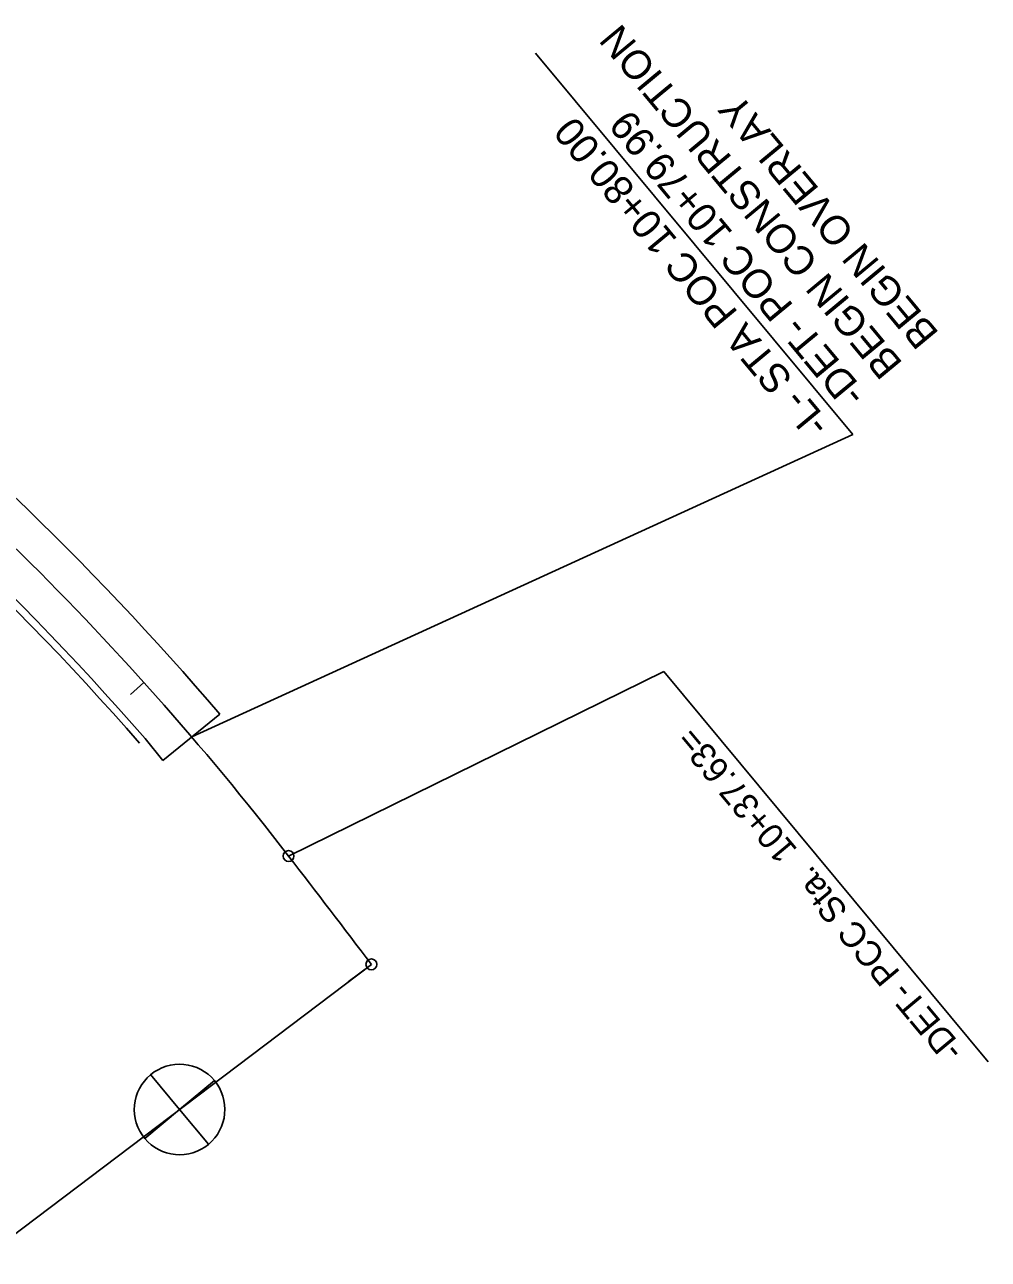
# Model space of a CAD drawing. Extents: x 2597390 to 2598563, y 852595 to 853909.
# Drawn here: x 2598297.5 to 2598563.3, y 852756.5 to 853097.3 of the extents above; entities that cross this region are included whole.
import ezdxf

# ---------------------------------------------------------------- set-up
doc = ezdxf.new("R2010")
doc.units = 0
for name, color, linetype in [('Prop DSN Text', 7, 'Continuous'), ('Prop EOT', 7, 'Continuous'), ('Prop Equation Symbol CELL', 7, 'Continuous'), ('Prop Horizontal Alignment', 7, 'Continuous'), ('Prop Horizontal Alignment Station Label', 7, 'Continuous'), ('Prop Horizontal Alignment Tick Large', 7, 'Continuous'), ('Prop Horizontal Alignment Tick Small', 7, 'Continuous'), ('Prop Lane Lines', 7, 'Continuous'), ('Prop Leader Line Medium', 7, 'Continuous'), ('Prop Paved Shoulder', 7, 'Continuous')]:
    doc.layers.add(name, color=color, linetype=linetype)

msp = doc.modelspace()

# ---------------------------------------------------------------- linework, layer by layer
at = {"layer": 'Prop EOT'}
for p, q in [((2598351.3, 852907), (2598335.58, 852894.18)), ((2598335.58, 852894.18), (2598330.68, 852900.27))]:
    msp.add_line(p, q, dxfattribs=at)
msp.add_arc((2597710.69, 852359.03), 823, 41.12046, 53.47068, dxfattribs=at)
at = {"layer": 'Prop Equation Symbol CELL'}
for p, q in [((2598332.2, 852807.45), (2598340.18, 852797.83)), ((2598349.8, 852805.82), (2598340.18, 852797.83)), ((2598340.18, 852797.83), (2598330.57, 852789.85)), ((2598340.18, 852797.83), (2598348.17, 852788.22))]:
    msp.add_line(p, q, dxfattribs=at)
for start, end in [(39.7011, 129.7056), (129.7011, 219.7056), (309.7011, 39.7056), (219.7011, 309.7056)]:
    msp.add_arc((2598340.18, 852797.83), 12.5, start, end, dxfattribs=at)
at = {"layer": 'Prop Horizontal Alignment'}
for centre, radius, start, end in [((2597710.69, 852359.03), 833, 37.64582, 53.47068), ((2595067.53, 850320.15), 4171.16, 37.12886, 37.64582)]:
    msp.add_arc(centre, radius, start, end, dxfattribs=at)
at = {"layer": 'Prop Horizontal Alignment Station Label'}
for p, q in [((2598370.26, 852867.81), (2598473.85, 852918.74)), ((2598563.34, 852810.97), (2598473.85, 852918.74)), ((2598393.11, 852837.9), (2598285.55, 852756.47))]:
    msp.add_line(p, q, dxfattribs=at)
for centre in [(2598370.26, 852867.81), (2598393.11, 852837.9)]:
    msp.add_circle(centre, 1.5, dxfattribs=at)
at = {"layer": 'Prop Horizontal Alignment Tick Large'}
msp.add_line((2598393.11, 852837.9), (2598386.73, 852833.08), dxfattribs=at)
at = {"layer": 'Prop Horizontal Alignment Tick Small'}
msp.add_line((2598330.36, 852915.72), (2598326.64, 852912.37), dxfattribs=at)
at = {"layer": 'Prop Lane Lines'}
msp.add_arc((2597710.69, 852359.03), 843, 40.54315, 51.83177, dxfattribs=at)
at = {"layer": 'Prop Leader Line Medium'}
for p, q in [((2598525.93, 852984.16), (2598438.44, 853089.52)), ((2598343.55, 852900.68), (2598525.93, 852984.16))]:
    msp.add_line(p, q, dxfattribs=at)
at = {"layer": 'Prop Paved Shoulder'}
msp.add_arc((2597710.69, 852359.03), 821, 41.12046, 53.47068, dxfattribs=at)

# ---------------------------------------------------------------- texts
at = {"layer": 'Prop DSN Text'}
for s, p in [('BEGIN CONSTRUCTION', (2598539.96, 853003.83)), ('BEGIN OVERLAY', (2598549.96, 853012.13)), ('-DET- POC 10+79.99', (2598529.96, 852995.52)), ('-L- STA POC 10+80.00', (2598519.96, 852987.22))]:
    msp.add_text(s, height=8, rotation=129.7067, dxfattribs=at).set_placement(p)
at = {"layer": 'Prop Horizontal Alignment Station Label'}
msp.add_text('-DET- PCC Sta.  10+37.63=', height=7, rotation=129.874, dxfattribs=at).set_placement((2598556.94, 852814.5))

doc.saveas('drawing.dxf')
